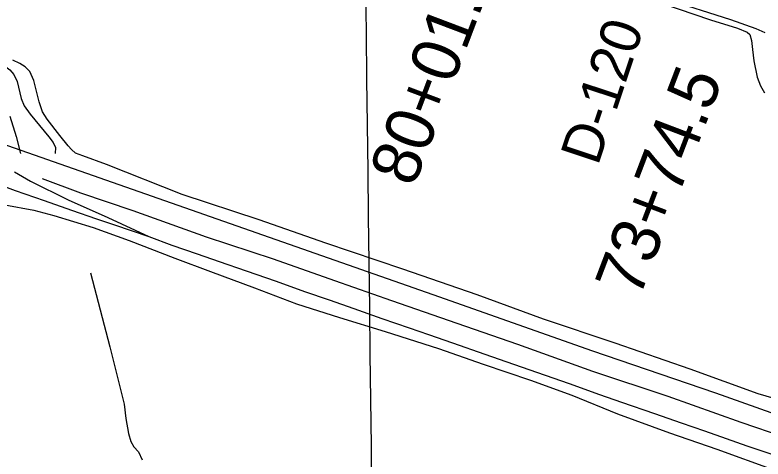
# Model space of a CAD drawing. Extents: x 3715084 to 3753216, y 488173 to 513963.
# Drawn here: x 3723845 to 3725388, y 497984 to 498901 of the extents above; entities that cross this region are included whole.
import ezdxf

# ---------------------------------------------------------------- set-up
doc = ezdxf.new("R2010")
doc.units = 0
for name, color, linetype in [('V-GRID-MAJR', 7, 'Continuous'), ('V-LEVE-TOET', 7, 'Continuous'), ('V-RAIL-TRAK', 7, 'Continuous'), ('V-RIVR-RANG-IDEN', 7, 'Continuous'), ('V-ROAD-CNTR', 7, 'Continuous'), ('V-SITE-VEGE', 7, 'Continuous'), ('V-SURV-IDEN', 7, 'Continuous'), ('V-TOPO-SHOR', 7, 'Continuous')]:
    doc.layers.add(name, color=color, linetype=linetype)

msp = doc.modelspace()

# ---------------------------------------------------------------- linework, layer by layer
at = {"layer": 'V-GRID-MAJR'}
msp.add_spline([(3724633.381, 493656.784), (3724559.356, 499715.322), (3724485.308, 505775.792), (3724411.259, 511836.27400000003), (3724411.236, 511838.193)], degree=3, dxfattribs=at)
at = {"layer": 'V-LEVE-TOET'}
msp.add_lwpolyline([(3723756.955, 499463.898), (3723872.042, 499414.66000000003), (3724001.56, 499365.696), (3724120.133, 499322.842), (3724251.021, 499273.004), (3724373.245, 499227.96), (3724521.852, 499171.694), (3724629.006, 499136.29000000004), (3724781.219, 499080.08900000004), (3724900.278, 499035.438), (3725044.262, 498984.947), (3725187.327, 498935.34), (3725321.252, 498891.875), (3725373.4990000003, 498873.021), (3725392.144, 498865.255)], dxfattribs=at)
at = {"layer": 'V-RAIL-TRAK'}
for points in [[(3723843.258, 498577.52400000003), (3723876.558, 498558.30700000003), (3723954.454, 498519.188), (3724036.356, 498482.855), (3724121.057, 498443.531)], [(3723807.469, 498552.364), (3723844.9450000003, 498538.868), (3723904.671, 498517.9), (3723961.448, 498497.781), (3724012.765, 498480.037), (3724049.9930000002, 498467.66500000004), (3724121.057, 498443.531), (3724168.535, 498425.941), (3724220.309, 498407.98), (3724265.727, 498391.93), (3724322.039, 498372.476), (3724383.342, 498351.539), (3724442.398, 498330.11100000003), (3724492.81, 498312.576), (3724543.668, 498295.27400000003), (3724601.591, 498274.049), (3724658.352, 498254.82800000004), (3724698.0870000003, 498241.152), (3724747.362, 498224.045), (3724814.569, 498200.966), (3724873.396, 498179.757), (3724938.563, 498157.315), (3724988.288, 498140.218), (3725050.978, 498117.504), (3725096.394, 498101.677), (3725164.287, 498078.162), (3725219.467, 498058.913), (3725267.603, 498042.461), (3725312.1240000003, 498026.167), (3725354.809, 498011.645), (3725410.666, 497992.408)]]:
    msp.add_lwpolyline(points, dxfattribs=at)
at = {"layer": 'V-ROAD-CNTR'}
for points in [[(3724721.5925178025, 498318.2013374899), (3722898.611163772, 498957.6830585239), (3722289.22838254, 499183.4286070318), (3721129.602701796, 499619.490734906)], [(3723834.113, 498692.447), (3723847.231, 498650.281), (3723855.919, 498614.934)], [(3728322.158316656, 497108.29575730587), (3728119.6737216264, 497153.64466660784), (3727963.244034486, 497194.57858473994), (3727833.314294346, 497234.6355046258), (3727668.8126233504, 497291.16039157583), (3727521.988916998, 497343.76728636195), (3727382.186196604, 497391.659190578), (3727208.277544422, 497452.95706798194), (3726976.23400851, 497533.7239064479), (3726762.0214369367, 497605.3437632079), (3726612.591735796, 497657.75665838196), (3726440.727079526, 497720.3975330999), (3726198.6655636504, 497801.36737116), (3725957.67104564, 497887.18019953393), (3725731.162498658, 497967.16903955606), (3725519.808921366, 498038.764896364), (3725291.300378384, 498120.03373382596), (3725035.391890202, 498207.82655823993), (3724721.5925178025, 498318.2013374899)]]:
    msp.add_lwpolyline(points, dxfattribs=at)
at = {"layer": 'V-SITE-VEGE'}
for p, q in [((3723823.468, 498509.237), (3723883.464, 498497.75)), ((3723883.464, 498497.75), (3723924.717, 498487.25800000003)), ((3723924.717, 498487.25800000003), (3724006.17, 498462.41999999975)), ((3724006.17, 498462.41999999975), (3724080.222, 498435.4109999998)), ((3724080.222, 498435.411), (3724174.7490000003, 498399.094)), ((3724174.7490000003, 498399.094), (3724248.143, 498371.1669999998)), ((3724248.143, 498371.1669999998), (3724339.007, 498337.9379999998)), ((3724339.007, 498337.938), (3724425.805, 498304.8550000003)), ((3724425.805, 498304.855), (3724514.316, 498276.543)), ((3724514.316, 498276.543), (3724608.2600000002, 498247.4329999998)), ((3724608.2600000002, 498247.4329999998), (3724718.329, 498212.31200000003)), ((3724718.329, 498212.31200000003), (3724810.975, 498180.24599999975)), ((3724810.975, 498180.24599999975), (3724908.38, 498146.91299999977)), ((3724908.38, 498146.91299999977), (3724993.779, 498116.2869999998)), ((3724993.779, 498116.2869999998), (3725088.352, 498077.71299999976)), ((3725088.352, 498077.71299999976), (3725195.122, 498038.24599999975)), ((3725195.122, 498038.246), (3725293.4450000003, 498004.25599999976)), ((3725293.4450000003, 498004.25599999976), (3725410.8710000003, 497961.833))]:
    msp.add_line(p, q, dxfattribs=at)
for points in [[(3723753.9020000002, 499445.265), (3723912.441, 499376.629), (3724026.077, 499332.326), (3724128.778, 499293.681), (3724277.268, 499243.275), (3724456.875, 499170.006), (3724607.145, 499120.987), (3724695.615, 499095.15400000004), (3724791.846, 499064.505), (3724914.554, 499017.67), (3725031.235, 498979.29000000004), (3725148.444, 498936.862), (3725280.1550000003, 498891.099), (3725335.529, 498873.658), (3725355.988, 498865.477), (3725361.485, 498861.069), (3725364.8850000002, 498848.503), (3725367.039, 498830.04600000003), (3725369.3000000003, 498806.177), (3725376.2490000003, 498772.923), (3725382.918, 498754.553), (3725391.753, 498740.737)], [(3723894.697, 498722.102), (3723883.483, 498766.103), (3723875.463, 498784.447), (3723865.802, 498794.19), (3723854.3910000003, 498801.19), (3723840.2800000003, 498807.688)], [(3725538.5100000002, 498071.754), (3725378.353, 498118.778), (3725237.9790000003, 498169.337), (3725083.555, 498223.238), (3724935.524, 498273.199), (3724798.316, 498323.369), (3724645.261, 498376.39400000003), (3724486.328, 498430.20900000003), (3724348.71, 498478.114), (3724189.3510000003, 498530.565), (3724033.429, 498592.107), (3723984.361, 498610.12200000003), (3723969.3570000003, 498616.151), (3723961.102, 498623.212), (3723954.19, 498630.749), (3723937.091, 498652.079), (3723911.1720000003, 498686.326), (3723901.409, 498701.477), (3723894.697, 498722.102)]]:
    msp.add_lwpolyline(points, dxfattribs=at)
at = {"layer": 'V-TOPO-SHOR'}
for points in [[(3723607.633, 498891.314), (3723684.222, 498857.201), (3723757.336, 498826.10000000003), (3723798.7260000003, 498808.075), (3723825.68, 498793.881), (3723833.661, 498787.876), (3723842.394, 498778.463), (3723849.177, 498763.541), (3723857.364, 498728.80700000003), (3723863.8140000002, 498713.537), (3723876.114, 498696.326), (3723914.629, 498649.857), (3723923.41, 498637.708), (3723928.401, 498627.2), (3723927.603, 498615.213)], [(3725751.7970000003, 497922.38300000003), (3725630.193, 497958.862), (3725520.705, 497998.73), (3725343.598, 498059.417), (3725192.794, 498112.933), (3725037.062, 498164.553), (3724882.597, 498220.707), (3724757.247, 498264.333), (3724622.366, 498310.935), (3724504.733, 498352.00200000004), (3724378.005, 498396.956), (3724239.54, 498442.137), (3724088.719, 498496.556), (3723980.644, 498533.293), (3723901.487, 498562.526)], [(3724000.626, 498368.931), (3724040.091, 498215.83900000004), (3724069.873, 498097.302), (3724073.148, 498067.588), (3724079.144, 498037.02400000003), (3724083.9820000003, 498019.972), (3724089.599, 498009.251), (3724099.7290000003, 497998.618), (3724107.253, 497982.518)]]:
    msp.add_lwpolyline(points, dxfattribs=at)

# ---------------------------------------------------------------- texts
at = {"layer": 'V-RIVR-RANG-IDEN'}
msp.add_text('D-120', height=83.00000000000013, rotation=71.59032571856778, dxfattribs=at).set_placement((3725047.5628554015, 498588.0192900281))
at = {"layer": 'V-SURV-IDEN'}
for s, height, rotation, p in [('80+01.2', 99.99999999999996, 69.26527780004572, (3724667.36905546, 498543.2773060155)), ('73+74.5', 99.99999999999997, 69.15861108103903, (3725132.9642623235, 498313.77046035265))]:
    msp.add_text(s, height=height, rotation=rotation, dxfattribs=at).set_placement(p)

doc.saveas('drawing.dxf')
